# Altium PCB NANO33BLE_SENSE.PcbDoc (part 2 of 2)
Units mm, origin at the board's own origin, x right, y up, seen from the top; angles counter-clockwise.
Board outline 43.18 x 17.78 mm, 4 copper layers (TOP, GND, SIG, BOTTOM), stack 1.586 mm thick; 73 components, 66 nets, 343 pads, 193 vias.
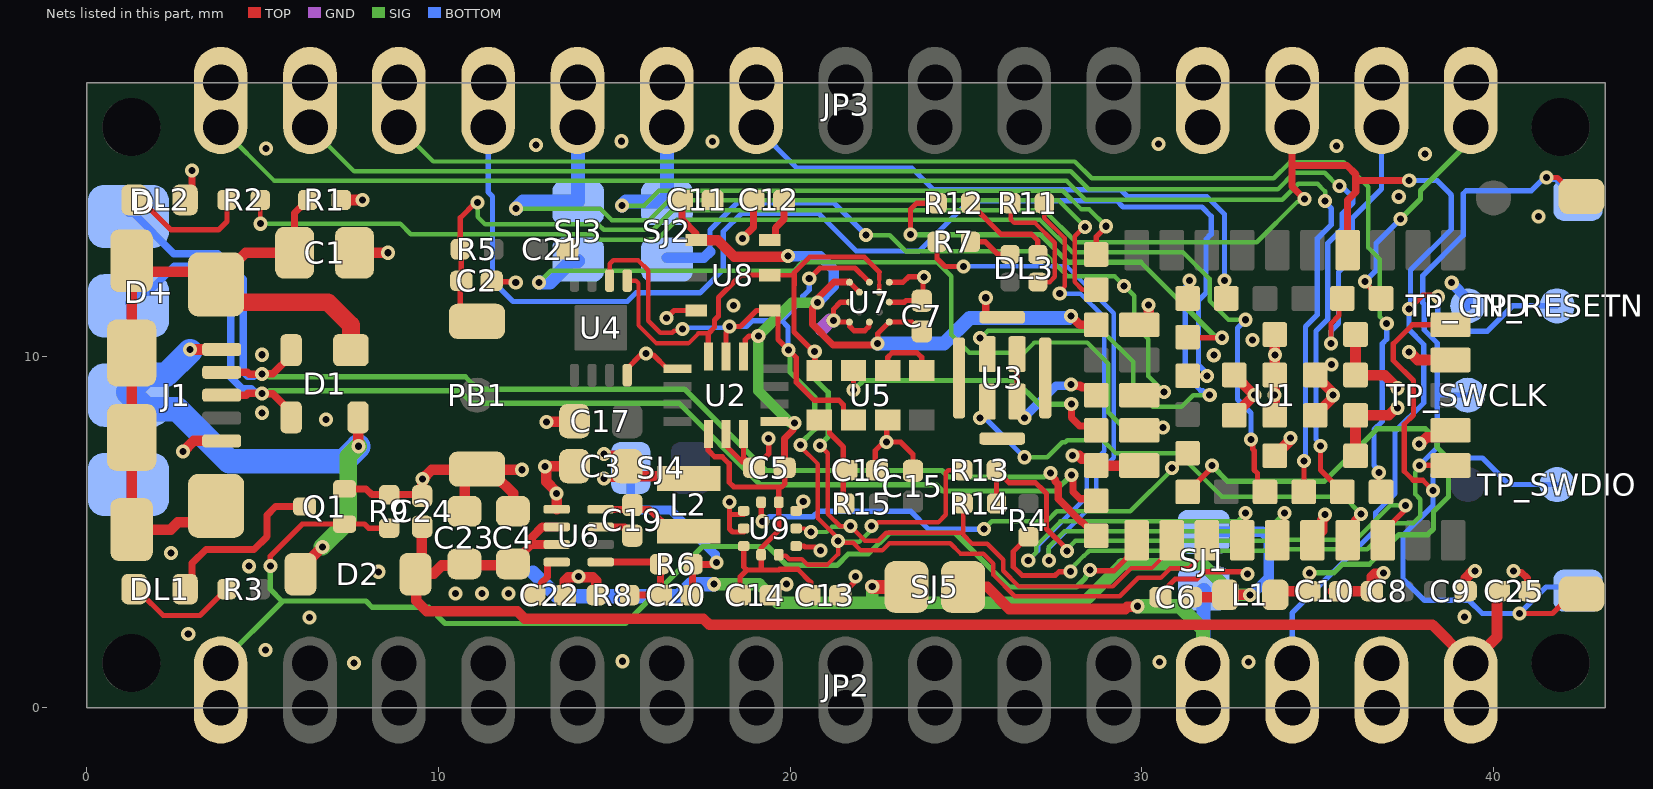
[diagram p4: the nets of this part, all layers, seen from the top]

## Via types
v1: diameter 0.4, hole 0.2, TOP to BOTTOM, tented both sides, 193 vias

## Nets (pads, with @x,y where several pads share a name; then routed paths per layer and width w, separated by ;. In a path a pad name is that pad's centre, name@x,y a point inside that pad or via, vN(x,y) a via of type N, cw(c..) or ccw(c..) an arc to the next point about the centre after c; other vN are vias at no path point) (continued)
D6~: JP3.9 U1.41 | length 16.8
  TOP w0.15: v1(32.352,12.149) 32.352,11.69 U1.41@32.402,11.64
  BOTTOM w0.15: JP3.9@19.035,16.51 20.202,15.343 23.461,15.343 24.073,14.732 29.398,14.732 29.591,14.538 31.847,14.538 32.352,14.034 v1(32.352,12.149)
D7: JP3.10 SJ2.2 U1.47 | length 18.9
  TOP w0.127: JP3.10@16.403,16.418 JP3.10@16.495,16.51
  TOP w0.15: U1.47@28.702,12.89 28.702,13.392 28.986,13.676 v1(28.986,13.694)
  SIG w0.127: v1(15.216,14.283) 15.853,14.283 16.274,14.704 27.753,14.704 28.285,14.172 28.508,14.172 v1(28.986,13.694)
  BOTTOM w0.4: v1(15.216,14.283) 15.333,14.4 SJ2.2@16.5,14.4 ; JP3.10@16.495,16.51 16.498,16.507 SJ2.2@16.498,14.402
D8: JP3.11 SJ3.2 U1.48 | length 23.2
  TOP w0.127: v1(28.387,13.678) 28.359,13.678 28.091,13.41 28.091,12.109 28.311,11.89 U1.48@28.702,11.89
  SIG w0.127: v1(12.205,14.195) 14.605,14.195 14.931,13.869 15.992,13.869 16.55,14.427 27.639,14.427 v1(28.387,13.678)
  BOTTOM w0.4: v1(12.205,14.195) 12.41,14.4 13.975,14.4 13.965,14.41 13.965,16.5 JP3.11@13.955,16.51
D9~: JP3.12 U1.44 | length 33.3
  TOP w0.15: U1.44@31.302,9.44 v1(31.852,9.44)
  BOTTOM w0.15: JP3.12@11.415,16.51 11.415,14.665 11.539,14.541 11.539,12.135 12.121,11.553 15.371,11.553 15.622,11.804 16.781,11.804 16.784,11.8 17.441,11.8 18.098,12.457 18.098,13.535 18.623,14.06 18.775,14.06 20.814,14.06 21.883,12.991 23.672,12.991 25.1,14.419 29.287,14.419 29.467,14.238 31.712,14.238 31.973,13.978 31.973,13.468 31.826,13.321 31.826,11.791 31.615,11.58 31.615,9.745 31.852,9.508 v1(31.852,9.44)
D10~: JP3.13 U1.36 | length 37.8
  TOP w0.15: v1(36.738,6.687) 36.738,6.204 U1.36@36.802,6.14
  SIG w0.127: JP3.13@8.875,16.51 9.851,15.535 14.359,15.535 16.091,15.535 28.098,15.535 28.576,15.056 33.755,15.056 34.212,15.513 35.741,15.513 36.438,14.816 36.438,13.088 36.765,12.761 36.765,11.127 v1(36.964,10.928)
  BOTTOM w0.15: v1(36.738,6.687) 36.738,6.755 36.599,6.893 36.599,7.911 36.839,8.15 36.839,10.359 36.964,10.484 v1(36.964,10.928)
GND: C1.1 C2.2 C3.1 C4.1 C5.2 C6.2 C7.1 C8.1 C9.2 C10.2 C11.2 C12.2 C13.2 C14.2 C15.1 C16.1 C17.1 C21.1 C22.1 C23.1 C24.2 C25.1 DL2.C J1.5 JP2.14 JP3.4 pad.USB_P@1.189,6.35 PB1.1 Q1.S R1.1 R8.1 R9.1 TP_GND.X U1.6 U1.12 U1.14 U1.26 U1.30 U1.53 U1.GND1 U1.GND2 U1.GND3 U1.GND4 U1.GND5 U1.GND6 U1.GND7 U1.GND8 U1.GND9 U1.GND10 U1.GND11 U1.GND12 U2.1 U2.6 U2.7 U3.5 U4.4 U5.6 U6.1 U7.A5 U7.C1 U7.C5 U7.E1 U7.E3 U8.6 U9.3 U9.5 U9.8 U9.9 | length 63.3
  TOP w0.15: C2.2@11.52,12.14 11.545,12.115 12.175,12.115 v1(12.2,12.09) ; U4.4@15.37,9.46 15.37,9.65 15.751,10.031 15.851,10.031 v1(15.899,10.079) 15.947,10.031 16.117,10.031 16.508,9.64 U2.1@17.002,9.64 ; v1(16.48,11.079) 16.702,11.3 U8.6@17.027,11.3 ; U2.6@18.177,7.79 18.227,7.74 18.227,7.405 18.639,6.993 C5.2@18.811,6.993 ; v1(18.28,5.85) 18.277,5.848 18.277,5.507 ; U2.7@18.678,7.79 18.678,7.127 C5.2@18.811,6.993 ; U9.9@18.682,5 18.365,5 18.277,5.088 18.277,5.507 ; U9.8@18.682,5.5 18.284,5.5 18.277,5.507 ; C5.2@18.878,6.993 C5.2@18.811,6.993 ; v1(19.391,7.664) 19.391,7.216 19,6.825 C5.2@18.977,6.825 18.977,6.827 C5.2@18.811,6.993 ; C14.2@19.447,3.205 19.513,3.205 19.776,3.468 19.853,3.468 v1(19.901,3.516) ; U9.3@20.172,4.6 20.396,4.6 20.421,4.575 20.702,4.575 20.801,4.476 v1(20.869,4.476) ; U9.5@20.172,5.6 20.197,5.6 20.327,5.73 20.327,5.817 v1(20.375,5.865) ; C13.2@21.426,3.205 21.451,3.205 21.812,3.566 21.812,3.684 v1(21.86,3.732) ; U7.E1@21.687,10.97 21.274,10.97 v1(21.232,11.012) 21.232,11.333 21.434,11.535 U7.C1@21.688,11.535 ; U7.E1@21.688,10.969 21.688,10.854 21.82,10.721 22.121,10.721 22.244,10.844 U7.E3@22.244,10.959 ; U7.E3@22.231,10.959 U7.E3@22.244,10.959 ; U7.E3@22.254,10.969 U7.E3@22.244,10.959 ; C16.1@22.423,6.825 22.423,7.315 22.617,7.508 22.629,7.508 22.677,7.557 23.144,7.557 23.494,7.207 C15.1@23.494,6.74 ; v1@22.75,7.557 22.75,8.167 U5.6@22.774,8.19 ; U7.C5@22.82,11.535 23.247,11.535 23.297,11.585 23.735,11.585 C7.1@23.745,11.575 23.779,11.609 23.779,12.221 v1(23.813,12.255) 23.366,12.255 23.212,12.101 U7.A5@22.82,12.101 ; U1.53@28.677,6.915 U1.53@28.702,6.89 ; C6.2@30.53,3.148 30.723,3.341 30.723,3.435 30.951,3.663 31.56,3.663 31.77,3.873 32.953,3.873 v1@33.009,3.816
  TOP w0.2: DL2.C@3,14.44 v1(3,15.275) ; Q1.S@7.335,6.225 7.944,6.225 8.109,6.06 R9.1@8.6,6.06 9.546,6.06 9.548,6.06 9.546,6.061 9.544,6.064 9.544,6.504 9.546,6.507 v1(9.548,6.508) ; v1(18.65,13.35) 18.65,13.357 18.957,13.664 C12.2@18.957,14.44 ; U3.5@25.563,11.149 v1@25.563,11.645 ; U3.5@25.755,11.106 U3.5@26.23,11.106 ; v1(40.57,3.89) 40.608,3.852 40.799,3.852 40.961,3.69 C25.1@40.961,3.309
  TOP w0.3: v1(2.74,7.287) 3.043,7.59 J1.5@3.84,7.59 ; R1.1@7.24,14.44 v1(7.84,14.44) ; C1.1@7.615,12.94 v1(8.565,12.94) ; C24.2@9.54,5.92 C24.2@9.55,5.91 ; C24.2@9.546,5.949 9.546,6.06 9.546,6.061 v1@9.546,6.507 ; v1(9.548,6.508) 9.81,6.77 11.088,6.77 10.745,6.427 10.745,5.565 10.74,5.57 C23.1@10.74,5.58 ; PB1.1@11.1,6.775 11.633,6.775 PB1.1@11.633,6.77 ; C4.1@12.12,5.57 12.13,5.56 C4.1@12.13,5.55 ; C4.1@12.125,5.57 12.125,6.097 11.633,6.589 PB1.1@11.633,6.77 ; v1(12.38,6.77) PB1.1@11.633,6.77 ; v1(13.073,8.127) 13.084,8.139 13.859,8.139 C17.1@13.87,8.15 ; U6.1@13.365,5.645 v1(13.365,6.095) 13.365,6.145 13.356,6.145 13.065,6.435 13.065,6.831 v1(13.037,6.859) 13.042,6.865 13.865,6.865 C3.1@13.87,6.87 ; C22.1@13.6,3.125 C22.1@13.6,3.205 13.6,3.618 13.697,3.715 14.392,3.715 14.49,3.617 R8.1@14.49,3.205 R8.1@14.49,3.125 ; v1(28.031,7.181) 28.051,7.162 28.224,7.162 28.295,7.09 28.502,7.09 U1.53@28.677,6.915 ; U1.53@28.702,6.89 U1.30@29.927,6.89 ; U1.26@29.927,10.89 29.997,10.89 30.197,11.09 v1(30.197,11.451) ; U1.GND12@32.622,9.465 U1.GND12@32.627,9.465 v1(33.202,8.89) U1.GND11@32.627,8.315 ; U1.GND7@33.777,7.165 34.227,7.615 v1(34.227,7.677) ; U1.GND8@33.777,8.315 v1(33.777,8.89) U1.GND9@33.777,9.465 33.783,9.471 v1(33.783,10.039) 33.783,10.609 U1.GND10@33.777,10.615 ; U1.6@34.852,4.765 35.127,5.04 35.127,5.339 35.213,5.425 v1(35.213,5.493) ; U1.GND5@34.927,8.315 35.434,8.822 v1(35.434,8.889) 35.386,8.937 35.386,9.006 U1.GND6@34.927,9.465 ; C10.2@35.435,3.312 35.439,3.316 36.536,3.316 C8.1@36.54,3.32 ; U1.GND1@36.077,7.165 U1.GND2@36.077,8.315 37.025,8.315 37.242,8.532 v1(37.269,8.532) ; U1.GND4@36.077,10.615 U1.GND3@36.077,9.465 36.087,9.455 36.903,9.455 v1(37.271,9.087) ; C8.1@36.47,3.39 C8.1@36.54,3.32 ; C8.1@36.542,3.322 C8.1@36.54,3.32 ; v1(36.87,3.84) 36.845,3.815 36.628,3.815 36.54,3.727 C8.1@36.54,3.32 ; v1(37.593,10.117) 37.62,10.117 37.847,9.89 U1.14@38.777,9.89 ; v1(37.888,7.509) 37.915,7.509 38.096,7.69 38.564,7.69 U1.12@38.77,7.897 ; C9.2@39.21,3.32 39.21,3.685 v1@39.415,3.89
  GND w0.4: 20.9,10.775 21.137,11.012 v1(21.232,11.012)
  BOTTOM w0.3: v1@38.806,12.082 39.268,11.619 TP_GND.X@39.268,11.43
  other v1: 7.6,1.275 15.23,1.325 30.498,1.309 33.038,1.309 5.088,1.647 2.889,2.102 6.342,2.564 39.17,2.59 10.49,3.249 11.24,3.249 11.99,3.249 13.99,3.733 33,3.8 8.294,3.869 39.47,3.89 4.611,4.027 2.4,4.4 22.745,7.557 6.8,8.2 4.99,8.39 35.393,9.765 4.99,10.04 32.047,10.026 33.144,10.465 18.393,11.437 25.563,11.661 38.812,12.087 41.283,13.974 37.306,14.533 38.053,15.746 5.1,15.9 35.534,15.97 12.771,16.002 30.48,16.037 15.21,16.11 17.8,16.1
INT_APDS: U1.52 U5.2 | length 8.2
  TOP w0.15: v1(21.801,9.042) U5.2@21.801,9.588 ; U5.2@22.001,9.588 U5.2@22.004,9.59
  TOP w0.2: v1(27.995,8.635) 27.995,8.252 28.227,8.02 28.572,8.02 U1.52@28.702,7.89
  SIG w0.15: v1@21.896,9.122 22.085,9.311 26.401,9.311 27.077,8.635 v1(27.995,8.635)
LB: R12.1 U1.43 | length 12.6
  TOP w0.15: v1(23.425,13.454) 23.425,14.175 23.6,14.35 R12.1@24.18,14.35 ; U1.43@31.302,10.54 31.318,10.524 v1(32.286,10.524)
  SIG w0.15: v1(23.425,13.454) 27.117,13.454 27.9,12.671 29.971,12.671 32.07,10.572 32.238,10.572 v1(32.286,10.524)
LG: R11.1 U1.4 | length 19.9
  TOP w0.127: R11.1@27.23,14.35 27.23,13.93 27.814,13.346 27.814,11.989 27.668,11.843 v1(27.668,11.778)
  TOP w0.15: U1.4@32.852,4.765 32.952,4.865 v1(32.952,5.535)
  SIG w0.127: v1(26.772,4.19) 27.004,4.422 27.004,4.615 27.688,5.299 32.717,5.299 v1(32.952,5.535)
  BOTTOM w0.127: v1(26.772,4.19) 27.054,4.472 27.054,4.622 28.431,5.999 28.431,6.797 28.93,7.296 28.93,11.104 28.255,11.778 v1(27.668,11.778)
LPS22HBTR_INT1: U1.46 U9.7 | length 13.8
  TOP w0.15: U9.7@19.177,5.745 19.177,5.343 v1(19.215,5.305) ; v1(30.861,6.82) 30.882,6.82 U1.46@31.302,7.24
  SIG w0.127: v1(25.514,5.091) 25.731,5.308 27.305,5.308 27.583,5.587 29.674,5.587 30.861,6.773 v1(30.861,6.82)
  BOTTOM w0.15: v1(19.215,5.305) 19.282,5.305 19.413,5.436 20.656,5.436 20.814,5.594 23.424,5.594 23.94,5.078 25.501,5.078 v1(25.514,5.091)
LR: R7.1 U1.5 | length 22.3
  TOP w0.15: R7.1@24.18,13.25 24.18,12.773 24.403,12.55 v1(24.93,12.55) ; U1.5@33.852,4.765 34.052,4.965 v1(34.052,5.535)
  SIG w0.127: v1(27.36,4.186) 27.36,4.58 27.802,5.022 33.54,5.022 v1(34.052,5.535)
  BOTTOM w0.127: v1(24.93,12.55) 27.876,12.55 29.207,11.219 29.207,7.115 28.708,6.616 28.708,5.884 27.36,4.536 v1(27.36,4.186)
MIC_PWR: U1.51 U3.1 U3.2 | length 4.4
  TOP w0.15: U3.1@26.455,8.706 U3.2@26.455,10.056
  TOP w0.25: U3.1@26.455,8.706 26.455,8.436 26.645,8.246 v1(26.665,8.246) ; v1(27.99,9.19) 28.019,9.161 28.248,9.161 28.294,9.115 28.477,9.115 U1.51@28.702,8.89
  BOTTOM w0.25: v1@26.672,8.272 27.561,9.161 27.961,9.161 v1(27.99,9.19)
MISO~: JP3.15 U1.34 | length 41.5
  TOP w0.15: U1.34@34.602,6.14 34.609,6.147 v1(34.609,7.016)
  SIG w0.127: JP3.15@3.81,16.51 5.339,14.981 14.589,14.981 15.861,14.981 27.868,14.981 28.4,14.449 33.996,14.449 34.445,14.898 34.996,14.898 35.211,14.683 35.211,14.411 v1(35.214,14.408)
  BOTTOM w0.15: v1(34.609,7.016) 34.652,7.058 34.652,10.84 34.991,11.179 34.991,13.34 35.39,13.739 35.39,14.196 35.214,14.372 v1(35.214,14.408)
MOSI: JP3.14 U1.35 | length 40
  TOP w0.15: v1(35.082,7.441) 35.082,6.76 U1.35@35.702,6.14
  SIG w0.127: JP3.14@6.35,16.51 7.603,15.258 14.474,15.258 15.976,15.258 27.983,15.258 28.492,14.749 33.872,14.749 34.336,15.213 35.201,15.213 35.581,14.834 v1(35.617,14.834)
  BOTTOM w0.15: v1(35.082,7.441) 35.082,7.509 34.952,7.638 34.952,10.716 35.291,11.055 35.291,13.216 35.69,13.615 35.69,14.05 36,14.36 36,14.509 35.676,14.834 v1(35.617,14.834)
NetC3_2: C3.2 C20.2 L2.2 R6.2 SJ4.1 | length 10
  TOP w0.2: v1(14.71,6.52) C3.2@15.37,6.52 ; v1(14.71,7.22) C3.2@15.37,7.22 ; C20.2@17.22,3.225 17.22,4.08 17.242,4.058 17.266,4.082 17.802,4.082 17.851,4.131 v1(17.905,4.131)
  TOP w0.25: C3.2@15.37,6.87 15.661,6.579 C3.2@15.729,6.579
  TOP w0.3: C3.2@15.729,6.579 17.111,6.579 L2.2@17.17,6.52
  BOTTOM w0.2: v1(14.71,6.52) SJ4.1@15.17,6.52 ; v1(14.71,7.22) 14.717,7.213 SJ4.1@15.077,7.213
  BOTTOM w0.25: SJ4.1@15.47,6.82 15.47,5.773 15.616,5.627 16.606,5.627 17.876,4.356 17.876,4.16 v1(17.905,4.131)
NetC10_1: C10.1 L1.2 U1.31 | length 16.8
  TOP w0.15: U1.31@31.302,6.14 31.997,6.836 v1(31.997,6.888) ; L1.2@33.798,3.213 L1.2@33.897,3.312 ; C10.1@34.765,3.312 34.767,3.315 34.767,3.837 v1(34.77,3.84)
  TOP w0.3: L1.2@33.897,3.312 C10.1@34.765,3.312
  SIG w0.15: v1(31.997,6.888) 32.441,6.444 35.195,6.444 36.684,7.934 38.064,7.934 38.4,7.598 38.4,7.401 38.717,7.084 38.717,6.002 38.291,5.576 38.291,5.089 38.127,4.925 37.313,4.925 36.809,4.42 36.806,4.42 36.468,4.083 35.709,4.083 35.466,3.84 v1(34.77,3.84)
NetC12_1: C12.1 U8.3 | length 1.4
  TOP w0.2: U8.3@19.35,13.266 19.474,13.266 19.582,13.375 19.582,13.649 19.827,13.894 C12.1@19.827,14.44
NetC16_2: C16.2 R15.1 U5.8 | length 2.4
  TOP w0.15: U5.8@21.034,8.05 21.119,7.965 21.119,7.814 21.514,7.419 R15.1@21.514,5.86
NetC19_1: C19.1 L2.1 U6.8 | length 3
  TOP w0.2: U6.8@14.615,5.645 15.345,5.645 15.515,5.815 15.695,5.635 16.005,5.635 16.62,5.02 L2.1@17.17,5.02
NetC19_2: C19.2 U6.7 | length 1
  TOP w0.2: U6.7@14.615,5.145 15.313,5.145 15.513,4.945 C19.2@15.515,4.945
NetC20_1: C20.1 R6.1 R8.2 U6.5 | length 3.4
  TOP w0.2: U6.5@14.615,4.145 R6.1@16.23,4.145 ; R8.2@15.44,3.205 C20.1@16.33,3.205 ; R6.1@16.29,4.085 16.31,4.065 C20.1@16.31,3.225
NetC22_2: C22.2 U6.4 | length 1.2
  TOP w0.2: C22.2@12.73,3.205 12.914,3.389 12.914,3.541 13.098,3.726 13.098,4.12 13.123,4.145 U6.4@13.177,4.145
NetDL1_A: DL1.A R3.1 | length 3.1
  TOP w0.15: DL1.A@1.55,3.375 1.55,3.253 2.176,2.626 3.223,2.626 3.972,3.375 R3.1@3.99,3.375
NetDL1_C: DL1.C Q1.D | length 5
  TOP w0.2: DL1.C@3,3.375 3,4.111 3.391,4.503 4.761,4.503 5.124,4.866 5.124,5.477 5.372,5.725 Q1.D@6.195,5.725
NetDL2_A: DL2.A R2.1 | length 3.5
  TOP w0.15: DL2.A@1.55,14.44 1.55,14.422 1.827,14.145 1.845,14.145 2.398,13.592 3.75,13.592 3.99,13.832 R2.1@3.99,14.44
NetDL3_2: DL3.2 R7.2 | length 1.3
  TOP w0.15: R7.2@25.13,13.25 25.555,13.25 25.91,12.895 DL3.2@26.255,12.895
NetDL3_3: DL3.3 R12.2 | length 2.8
  TOP w0.15: R12.2@25.13,14.35 25.13,14.335 26,13.465 26.861,13.465 27.045,13.282 DL3.3@27.045,12.895
NetDL3_4: DL3.4 R11.2 | length 3.5
  TOP w0.127: R11.2@26.28,14.35 26.28,13.874 26.368,13.787 26.964,13.787 27.528,13.222 27.528,12.255 27.378,12.105 DL3.4@27.045,12.105
NetJP2_12: JP2.12 SJ1.2 SJ5.2 | length 10.5
  TOP w0.3: SJ5.2@24.87,3.439 25.608,3.439 26.237,2.81 29.528,2.81 29.588,2.87 29.856,2.87 v1(29.875,2.889)
  SIG w0.4: v1(29.875,2.889) 31.072,2.889 31.735,2.227 JP2.12@31.735,1.27
  BOTTOM w0.4: JP2.12@31.75,1.27 31.756,1.276 31.756,3.344 SJ1.2@31.762,3.35
NetR2_2: R2.2 U1.33 | length 36
  TOP w0.127: v1(4.94,13.765) R2.2@4.94,14.44
  TOP w0.15: v1(33.105,7.631) 33.152,7.584 33.152,7.36 33.195,7.317 33.195,6.766 33.29,6.671 33.29,6.352 U1.33@33.502,6.14
  SIG w0.127: v1(4.94,13.765) 8.923,13.765 9.219,13.469 14.431,13.469 14.585,13.315 16.222,13.315 16.779,13.873 27.106,13.873 28.019,12.959 31.165,12.959 31.927,12.197 31.927,11.573 32.465,11.035 v1(32.952,11.035)
  BOTTOM w0.15: v1(32.952,11.035) 32.719,10.802 32.719,8.772 33.105,8.386 v1(33.105,7.631)
NetSJ2_1: SJ2.1 U1.28 | length 19.2
  TOP w0.2: U1.28@29.927,8.89 29.981,8.944 30.599,8.944 v1(30.637,8.983)
  SIG w0.127: v1(22.157,13.44) 22.835,13.44 23.292,12.983 27.179,12.983 27.888,12.275 29.225,12.275 v1(29.5,12) 29.783,11.717 29.783,10.891 30.19,10.485 30.19,9.43 v1(30.637,8.983)
  BOTTOM w0.15: 17.723,12.971 17.723,13.585 18.504,14.365 21.232,14.365 v1(22.157,13.44)
  BOTTOM w0.3: SJ2.1@16.5,12.795 17.547,12.795 17.723,12.971
NetSJ3_1: SJ3.1 U1.29 | length 24.1
  TOP w0.15: U1.29@29.927,7.89 30.007,7.97 v1(30.599,7.97)
  SIG w0.127: v1(12.856,12.089) 13.198,12.431 20.113,12.431 20.35,12.669 24.184,12.669 24.58,12.273 24.58,10.613 25.091,10.102 26.663,10.102 26.948,10.388 28.447,10.388 29.045,9.79 29.045,8.405 29.119,8.331 29.596,7.854 30.024,7.854 30.141,7.97 v1(30.599,7.97)
  BOTTOM w0.4: v1(12.856,12.089) 13.167,12.089 13.778,12.7 SJ3.1@13.975,12.7
NetU5_3: U5.3 U5.4 | length 1.8
  TOP w0.15: U5.3@22.774,9.59 22.774,9.965 22.905,10.097 23.612,10.097 23.744,9.965 U5.4@23.744,9.59
PDMCLK: U1.42 U3.3 | length 12.6
  TOP w0.15: v1(25.395,10.516) 25.605,10.306 U3.3@25.605,10.056 ; U1.42@31.302,11.64 31.352,11.69 v1(31.352,12.149)
  SIG w0.127: v1@25.532,10.632 25.626,10.726 28.868,10.726 29.753,9.842 29.753,9.118 30.314,8.558 31.129,8.558 31.462,8.891 v1(31.931,8.891)
  BOTTOM w0.15: v1(31.352,12.149) 31.352,12.081 31.236,11.965 31.236,9.455 31.676,9.015 31.74,9.015 31.864,8.891 v1(31.931,8.891)
PDMDIN: U1.7 U3.4 | length 13.7
  TOP w0.15: v1(25.395,8.246) 25.605,8.456 U3.4@25.605,8.706
  TOP w0.2: U1.7@35.852,4.765 36.046,4.959 36.046,5.334 v1(36.228,5.516)
  SIG w0.127: v1(26.659,7.125) 27.31,7.125 27.74,7.555 27.821,7.555 27.879,7.613 28.888,7.613 29.268,7.233 31.049,7.233 32.275,6.007 35.737,6.007 v1(36.228,5.516)
  BOTTOM w0.15: v1@25.555,8.23 v1(26.659,7.125)
R_PULLUP: R13.2 R14.2 U1.8 | length 15.9
  TOP w0.15: R13.2@25.863,6.76 R13.2@25.867,6.757 ; R14.2@25.87,5.81 25.867,5.813 R13.2@25.867,6.757 ; v1@27.875,4.51 27.87,4.51 27.294,5.086 27.294,6.096 27.125,6.265 27.114,6.265 26.978,6.401 26.222,6.401 R13.2@25.867,6.757 ; U1.8@36.852,4.765 36.852,4.99 37.446,5.584 37.446,5.709 v1(37.494,5.757)
  SIG w0.127: v1@27.875,4.51 28.11,4.745 33.864,4.745 33.903,4.784 36.097,4.784 37.07,5.757 v1(37.494,5.757)
  other v1: 27.875,4.46
RESETN: C2.1 JP2.13 JP3.3 PB1.2 R5.1 TP_RESETN.X U1.19 | length 59.4
  TOP w0.15: C2.1@10.625,12.14 10.625,11.402 PB1.2@11.037,10.99 ; R5.1@10.625,13.04 10.625,13.935 11.055,14.365 v1(11.114,14.365) ; C2.1@10.65,12.14 R5.1@10.65,13.04 ; v1(37.594,11.341) 37.991,11.738 38.369,11.738 v1(38.417,11.69)
  TOP w0.2: JP3.3@34.275,16.51 34.521,16.264 34.275,16.017 34.275,15.418 ; v1(34.621,14.473) 34.275,14.819 34.275,15.418 ; U1.19@35.852,13.015 35.852,14.432 36.083,14.663 36.083,14.917 ; v1(37.604,14.995) 36.161,14.995 36.083,14.917 ; 34.275,15.418 35.836,15.418 36.083,15.171 36.083,14.917
  SIG w0.127: v1(11.114,14.365) 11.114,13.967 11.336,13.746 14.546,13.746 14.7,13.592 16.107,13.592 16.665,14.15 27.221,14.15 28.134,13.236 33.266,13.236 34.413,14.383 34.458,14.383 34.547,14.473 v1(34.621,14.473)
  BOTTOM w0.15: JP2.13@34.275,1.27 34.275,2.695 36.653,5.073 36.653,5.547 37.2,6.094 37.2,7.855 38.018,8.673 38.018,10.33 37.594,10.754 v1(37.594,11.341) 37.642,11.389 37.642,12.447 38.798,13.602 38.798,14.566 38.78,14.584 38.78,14.612 38.397,14.995 v1(37.604,14.995) ; v1(38.417,11.69) 38.417,11.066 38.778,10.705 39.82,10.705 40.545,11.43 TP_RESETN.X@41.808,11.43
RX: JP3.2 U1.38 | length 8.2
  TOP w0.15: v1(35.377,10.36) 35.377,10.922 35.607,11.153 35.607,11.546 U1.38@35.702,11.64
  BOTTOM w0.15: v1(35.377,10.36) 35.377,10.716 35.591,10.93 35.591,12.392 35.99,12.792 35.99,13.926 36.815,14.75 JP3.2@36.815,16.51
SCK: JP2.1 Q1.G R9.2 U1.1 | length 35.2
  TOP w0.15: v1(5.223,4.034) 5.223,4.315 6.133,5.225 Q1.G@7.335,5.225 7.899,5.225 8.014,5.11 R9.2@8.6,5.11 ; v1(28.526,3.916) 28.544,3.899 29.211,3.899 29.852,4.54 U1.1@29.852,4.765
  SIG w0.15: JP2.1@3.81,1.27 5.578,3.038 7.941,3.038 8.117,2.862 9.727,2.862 10.192,2.397 15.322,2.397 17.512,4.586 19.376,4.586 19.911,4.051 21.33,4.051 21.654,4.375 22.224,4.375 22.822,4.973 24.691,4.973 26.225,3.439 28.141,3.439 28.397,3.695 28.397,3.719 28.526,3.849 v1(28.526,3.916) ; v1(5.223,4.034) 5.223,3.363 5.563,3.023
SCL1: R13.1 U1.3 U2.13 U4.6 U5.7 U7.A3 U8.1 U9.2 | length 44.7
  TOP w0.127: U4.6@14.87,12.15 14.87,12.63 14.97,12.73 15.678,12.73 15.967,12.441 15.967,11.007 16.309,10.665 16.652,10.665 16.709,10.722 16.886,10.722 v1(16.939,10.774) ; U9.2@19.677,4.355 19.706,4.326 19.88,4.326 19.977,4.229 20.338,4.229 20.504,4.062 21.052,4.062 21.363,4.374 v1@21.363,4.691 ; v1(20.293,7.47) 20.293,7.433 20.793,6.933 20.793,5.389 21.254,4.929 21.254,4.924 21.363,4.814 v1(21.363,4.74) 21.412,4.691 21.798,4.691 22.013,4.475 22.618,4.475 22.825,4.682 24.551,4.682 24.846,4.388 25.49,4.388 25.781,4.096 25.781,3.78 26.387,3.174 29.377,3.174 29.903,3.699 30.545,3.699 30.809,3.963 31.327,3.963 31.577,4.213 31.577,4.49 U1.3@31.852,4.765 ; v1(22.315,5.169) 22.389,5.169 22.501,5.281 24.218,5.281 24.425,5.488 24.425,6.686 24.499,6.76 R13.1@25.013,6.76
  TOP w0.15: U2.13@18.177,9.99 18.177,10.672 18.279,10.774 v1(18.279,10.841) 18.588,10.841 19.047,11.3 19.557,11.3 19.657,11.2 19.657,10.475 20.177,9.955 20.177,9.255 20.685,8.747 21.387,8.747 21.519,8.616 21.519,8.415 21.744,8.19 U5.7@21.775,8.19 ; v1(20.545,12.205) 20.847,12.507 21.848,12.507 U7.A3@22.254,12.101 ; U5.7@21.975,8.19 U5.7@22.004,8.19
  SIG w0.127: v1(21.363,4.74) 21.387,4.717 21.965,4.717 22.263,5.014 22.263,5.117 v1(22.315,5.169)
  SIG w0.15: v1(19.953,10.179) 19.999,10.133 19.999,9.541 20.698,8.841 20.698,8.602 20.7,8.6 20.7,7.921 20.293,7.513 v1(20.293,7.47)
  BOTTOM w0.127: v1(16.939,10.774) 16.972,10.808 18.245,10.808 v1(18.279,10.841)
  BOTTOM w0.15: v1(18.279,10.841) 18.762,10.841 18.931,11.01 19.705,11.01 19.763,11.01 ; v1(19.953,10.179) 19.943,10.189 19.943,10.829 19.763,11.01 ; v1(20.545,12.205) 20.545,11.884 20.361,11.7 20.361,11.608 19.763,11.01
SDA1: R14.1 U1.2 U2.14 U4.5 U5.1 U7.B4 U8.2 U9.4 | length 33.9
  TOP w0.108: 22.537,12.028 22.537,12.168
  TOP w0.127: U4.5@15.37,12.15 15.615,12.15 15.69,12.075 15.69,10.873 16.202,10.361 17.11,10.361 17.394,10.645 17.677,10.645 ; U8.2@19.427,12.3 20.12,12.3 ; U9.4@20.172,5.1 20.424,5.1 20.524,5 v1(20.597,5) ; v1(20.846,7.465) 21.075,7.236 21.075,5.514 21.423,5.166 v1(21.719,5.166) 22.129,4.755 22.507,4.755 22.733,4.981 24.92,4.981 ; U7.B4@22.537,11.818 22.537,12.028 ; 22.537,12.168 22.537,12.393 ; R14.1@24.92,5.81 24.92,4.919 25.174,4.665 25.604,4.665 26.058,4.211 26.058,3.894 26.502,3.451 29.171,3.451 29.696,3.976 30.288,3.976 30.852,4.54 U1.2@30.852,4.765
  TOP w0.15: U2.14@17.677,9.99 17.677,10.645 17.854,10.822 17.854,11.029 17.963,11.137 17.963,11.663 18.608,12.308 19.419,12.308 U8.2@19.427,12.3 ; U5.1@20.926,9.59 20.701,9.815 v1(20.701,10.136) 20.665,10.136 20.113,10.689 20.113,12.022 20.12,12.029 20.12,12.3 20.12,12.381 20.56,12.821 22.109,12.821 22.537,12.393
  SIG w0.127: v1(20.597,5) 21.038,5 21.192,5.154 21.706,5.154 v1(21.719,5.166)
  SIG w0.15: v1(20.701,10.136) 20.701,9.803 20.57,9.673 20.57,9.486 21.082,8.974 21.082,7.702 v1(20.846,7.465)
SHIELD: C1.2 D1.1 J1.M1 J1.M2 J1.M3 J1.M4 J1.M5 J1.M6 R1.2 | length 21.2
  TOP w0.2: C1.2@5.915,12.94 5.915,14.072 6.175,14.332 R1.2@6.175,14.44
  TOP w0.3: J1.M2@1.28,12.71 J1.M5@1.28,10.09 J1.M6@1.28,7.69 J1.M3@1.28,5.07 2.39,5.07 2.596,5.276 J1.M4@3.213,5.276 ; J1.M2@1.588,12.402 3.316,12.402 J1.M1@3.68,12.037 3.68,12.091 4.529,12.94 C1.2@5.915,12.94
  TOP w0.5: J1.M1@3.68,12.037 4.181,11.537 6.863,11.537 7.515,10.885 D1.1@7.515,10.17
SWCLK: pad.JTAG_PAD@42.403,14.444 pad.JTAG_PAD@42.503,14.544 R4.1 TP_SWCLK.X U1.11 | length 29.6
  TOP w0.15: R4.1@26.779,4.86 26.764,4.86 26.347,4.443 26.347,4.014 26.6,3.761 27.536,3.761 27.647,3.871 v1(27.972,3.871) ; v1(37.895,6.897) 38.77,6.897 U1.11@38.777,6.89 ; v1(41.511,15.079) 41.818,15.079 42.253,14.644 pad.JTAG_PAD@42.303,14.644
  SIG w0.127: v1(27.972,3.871) 27.972,3.941 28.113,4.082 28.113,4.087 28.355,4.33 28.368,4.33 28.507,4.468 34.011,4.468 34.05,4.507 36.41,4.507 37.158,5.255 37.72,5.255 37.919,5.454 37.919,5.933 37.772,6.08 37.772,6.705 37.895,6.829 v1(37.895,6.897)
  BOTTOM w0.15: v1(37.895,6.897) 38.4,7.401 38.4,8.892 ; TP_SWCLK.X@39.266,8.892 38.4,8.892 ; pad.JTAG_PAD@42.003,14.644 42.003,14.793 41.795,15.001 41.795,15.03 41.628,15.03 41.579,15.079 41.453,15.079 41.08,14.707 39.228,14.707 39.14,14.619 39.14,13.44 37.992,12.292 37.992,11.514 38.032,11.474 38.032,10.741 38.4,10.372 38.4,8.892
SWDIO: pad.JTAG_PAD@42.403,3.336 pad.JTAG_PAD@42.503,3.236 TP_SWDIO.X U1.15 | length 21.7
  TOP w0.15: v1(38.277,6.183) 37.988,6.472 37.719,6.472 37.463,6.728 37.463,8.065 37.723,8.325 37.723,9.307 37.149,9.881 37.149,10.349 37.69,10.89 U1.15@38.777,10.89 ; v1(40.743,2.681) 41.676,2.681 42.131,3.136 pad.JTAG_PAD@42.303,3.136
  BOTTOM w0.15: TP_SWDIO.X@41.808,6.35 40.441,6.35 39.686,7.105 38.745,7.105 38.277,6.637 v1(38.277,6.183) 38.277,5.758 37.427,4.908 37.427,3.665 38.035,3.056 39.305,3.056 39.68,2.681 v1(40.743,2.681) 41.498,3.436 pad.JTAG_PAD@42.403,3.436
TX: JP3.1 U1.37 | length 6.3
  TOP w0.15: v1(36.351,12.127) 36.351,12.091 U1.37@36.802,11.64
  SIG w0.15: v1(37.352,13.899) 37.922,14.469 37.922,14.712 39.355,16.146 JP3.1@39.355,16.51
  BOTTOM w0.15: v1(36.351,12.127) 36.657,12.433 36.657,13.204 v1(37.352,13.899)
USB_N: D1.2 D-.X J1.2 pad.USB_N U1.55 | length 35.4
  TOP w0.21: J1.2@3.84,9.54 4.574,9.54 4.624,9.49 v1(4.99,9.49) 5,9.5 5.295,9.5 D1.2@5.815,10.02 ; v1(27.399,6.681) 27.399,6.629 27.544,6.485 27.544,6.435 27.624,6.355 27.624,5.944 28.283,5.285 28.307,5.285 U1.55@28.702,4.89
  SIG w0.15: v1@5.038,9.442 5.176,9.442 5.203,9.415 10.765,9.415 11.117,9.063 17,9.063 19.315,6.747 24.315,6.747 24.499,6.563 27.214,6.563 27.332,6.681 v1(27.399,6.681)
  BOTTOM w0.21: pad.USB_N@1.189,14.058 1.335,14.058 2.476,12.916 3.722,12.916 4.455,12.184 4.455,9.553 4.578,9.43 4.752,9.43 4.775,9.454 4.954,9.454 v1(4.99,9.49)
USB_P: D1.3 D+.X J1.3 pad.USB_P@1.189,11.43 U1.54 | length 35.1
  TOP w0.21: J1.3@3.84,8.89 4.534,8.89 4.584,8.94 v1(4.99,8.94) 5,8.93 5.295,8.93 D1.3@5.815,8.41 ; v1(27.999,6.623) 28.044,6.578 28.044,6.143 28.247,5.94 28.651,5.94 U1.54@28.702,5.89
  SIG w0.15: v1@5.038,8.988 5.176,8.988 5.203,9.015 10.599,9.015 10.951,8.663 16.834,8.663 19.149,6.347 24.15,6.347 24.334,6.163 27.539,6.163 v1(27.999,6.623)
  BOTTOM w0.21: pad.USB_P@1.189,11.518 1.487,11.816 pad.USB_P@1.783,11.816 ; pad.USB_P@1.783,11.849 2.49,12.556 3.573,12.556 4.095,12.035 4.095,9.404 4.428,9.07 4.682,9.07 4.775,8.976 4.954,8.976 v1(4.99,8.94)
VDD_ENV: C5.1 C7.2 C11.1 C13.1 C14.1 U1.49 U2.5 U2.8 U2.12 U7.A1 U7.B2 U7.E5 U8.4 U9.1 U9.6 U9.10 | length 37.6
  TOP w0.15: U2.5@17.677,7.79 17.677,7.315 17.853,7.139 18.069,7.139 18.27,6.938 18.27,6.412 18.402,6.28 19.669,6.28 ; C14.1@18.577,3.205 18.577,3.726 18.77,3.918 ; U2.12@18.678,9.99 18.723,10.035 18.723,10.465 18.832,10.574 v1(19.096,10.574) ; U9.10@18.682,4.5 18.682,4.006 18.77,3.918 ; U2.8@19.752,8.14 19.773,8.12 20.007,8.12 20.028,8.099 v1(20.123,8.099) ; C5.1@19.847,6.825 19.847,6.368 19.759,6.28 19.669,6.28 ; C13.1@20.589,3.322 20.589,3.57 20.218,3.941 19.709,3.941 19.687,3.918 19.177,3.918 ; U7.A1@21.684,12.105 U7.A1@21.688,12.101 U7.B2@21.971,11.818 ; v1@22.451,10.318 v1(22.489,10.356) 22.489,10.638 U7.E5@22.82,10.969 23.456,10.969 23.505,10.92 23.745,10.92 C7.2@23.745,10.705 ; 18.77,3.918 19.177,3.918 ; 19.177,3.918 U9.1@19.177,4.355 19.177,4.54 19.677,5.04 U9.6@19.677,5.845 19.677,6.273 19.669,6.28
  TOP w0.2: C11.1@16.927,14.44 16.927,13.891 17.327,13.491 U8.4@17.327,13.3 ; C5.1@19.847,6.825 19.843,6.829 19.843,7.656 20.085,7.898 20.085,8.061 v1(20.123,8.099) ; U7.A1@21.684,12.105 21.246,12.105 20.725,11.584 v1(20.786,11.524) 20.635,11.373 20.635,10.907 21.224,10.318 v1@22.451,10.318
  TOP w0.25: v1(27.99,11.14) 28.24,10.89 U1.49@28.702,10.89
  TOP w0.3: U8.4@17.327,13.3 17.939,13.3 18.416,12.823 19.854,12.823 19.857,12.825 19.922,12.825 v1(19.941,12.845)
  SIG w0.3: v1(20.123,8.099) 20.104,8.118 19.988,8.118 19.096,9.011 v1(19.096,10.574) 20.046,11.524 v1(20.786,11.524)
  BOTTOM w0.3: v1(19.941,12.845) 20.855,12.845 21.245,12.455 21.245,11.983 v1(20.786,11.524)
  BOTTOM w0.4: v1(22.489,10.356) 24.379,10.356 25.109,11.086 27.936,11.086 v1(27.99,11.14)
VIN: C4.2 C23.2 C24.1 C25.2 D2.C JP2.15 U6.2 U6.3 | length 40.3
  TOP w0.2: JP2.15@39.355,1.27 JP2.15@39.443,1.358
  TOP w0.25: C4.2@12.12,4.22 12.222,4.22 12.647,4.645 ; U6.3@13.365,4.645 12.647,4.645 ; U6.2@13.365,5.145 12.955,5.145 12.647,4.838 12.647,4.645
  TOP w0.3: D2.C@9.375,3.82 9.524,3.969 9.524,5.034 C24.1@9.54,5.05 ; C4.2@12.12,4.07 12.104,4.054 10.756,4.054 10.74,4.07 10.718,4.048 10.092,4.048 9.865,3.82 9.524,3.82 9.375,3.671 9.375,3.04 9.666,2.749 12.245,2.749 12.461,2.533 17.535,2.533 17.708,2.36 38.265,2.36 39.195,1.43 JP2.15@39.37,1.43 ; JP2.15@39.443,1.358 40.1,2.015 C25.2@40.1,3.3
VUSB: C6.1 D1.4 D2.A J1.1 L1.1 pad.USB_P@1.189,8.89 SJ1.1 SJ5.1 | length 44.7
  TOP w0.3: v1(2.938,10.187) v1(2.938,10.187) 3.838,10.189 J1.1@3.84,10.19 ; D2.A@6.08,3.8 6.08,3.955 v1(6.7,4.575) ; D1.4@7.715,8.26 7.721,8.254 7.721,7.444 v1(7.726,7.438) ; C6.1@31.4,3.148 32.313,3.148 L1.1@32.378,3.213 v1(33.073,3.213)
  TOP w0.4: v1(22.337,3.448) 22.345,3.439 SJ5.1@23.36,3.439
  SIG w0.35: v1(17.836,3.515) 19.124,3.515 19.649,2.99 22.251,2.99 ; v1@22.355,3.429 v1(22.337,3.448) 22.334,3.444 22.334,3.073 22.251,2.99 ; v1(33.073,3.213) 32.606,3.213 31.739,4.08 29.432,4.08 28.342,2.99 22.251,2.99
  SIG w0.5: v1(6.7,4.575) 7.438,5.313 7.438,7.149 v1(7.726,7.438)
  BOTTOM w0.3: SJ1.1@31.762,5.05 31.805,5.007 33.433,5.007 33.608,4.831 33.608,3.701 33.207,3.3 33.187,3.3 33.1,3.213 v1(33.073,3.213)
  BOTTOM w0.4: 12.691,3.851 13.37,3.173 16.836,3.173 17.179,3.515 v1(17.836,3.515)
  BOTTOM w0.7: v1@2.938,10.143 2.262,9.466 1.677,9.466 1.189,8.978 1.675,8.492 2.574,8.492 4.053,7.013 7.316,7.013 7.726,7.423 v1(7.726,7.438)
pads on no net: Fiducial_1.1 Fiducial_2.1 J1.4 U1.13 U1.45 U2.2 U2.3 U2.10 U2.11 U4.1 U4.2 U4.3 U4.7 U4.9 U6.6 U7.D2 U7.D4 U8.5

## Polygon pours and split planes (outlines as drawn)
GND on BOTTOM "GND_BOT" (solid, remove dead copper, pour order 19): 0,0 0,17.78 43.18,17.78 43.18,0
VUSB on BOTTOM "VUSB_POL" (solid, remove dead copper, pour order 17): 6.434,4.731 7.143,5.44 16.569,5.44 17.919,4.09 18.87,4.09 19.27,3.89 19.27,3.29 18.995,3.015 6.434,3.015
GND on GND "GND_2" (solid, remove dead copper, pour order 15): 0,17.78 0,0 43.18,0 43.18,17.78
GND on TOP "GND_TOP" (solid, remove dead copper, pour order 16): 0.091,0.425 0.091,18.205 43.271,18.205 43.271,0.425
GND on SIG "GND_3" (solid, remove dead copper, pour order 18): 0,0 0,17.78 43.18,17.78 43.18,0

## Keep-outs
TOP:
  rectangle: 21.4,10.396 23.6,12.596
GND:
  rectangle: 21.4,10.396 23.6,12.596
SIG:
  rectangle: 21.4,10.396 23.6,12.596
BOTTOM:
  rectangle: 21.4,10.396 23.6,12.596

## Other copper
TOP:
  pour cut-out: 43.162,4.137 39.352,4.137 39.352,13.633 43.162,13.633
GND:
  pour cut-out: 43.162,4.137 39.352,4.137 39.352,13.633 43.162,13.633
SIG:
  pour cut-out: 43.162,4.137 39.352,4.137 39.352,13.633 43.162,13.633
BOTTOM:
  region: 336 vertices and 0 holes, not listed, extent 0.795,2.687 1.791,3.586
  region: 243 vertices and 1 holes, not listed, extent 0.773,3.776 1.811,4.486
  pour cut-out: 15.597,14.407 17.437,14.407 17.437,12.599 15.597,12.599
  pour cut-out: 13.075,14.404 14.915,14.404 14.915,12.596 13.075,12.596
  pour cut-out: 43.162,4.137 39.352,4.137 39.352,13.633 43.162,13.633

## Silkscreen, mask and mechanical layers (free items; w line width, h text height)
Top Overlay:
  drawing of 44 lines, arcs and shapes, not listed
Bottom Overlay:
  drawing of 267 lines, arcs and shapes, not listed
Bottom Solder:
  rectangle: 15.394,6.085 17.341,7.555
Top 3D Body:
  the board outline again, w0.01
Route Tool Path:
  lines w2: -1,1 -1,0 ccw(c0,0) 0,-1 43.18,-1 ccw(c43.18,0) 44.18,0 44.18,6.5 ; -1,5 -1,13 ; -1,17 -1,17.78 cw(c0,17.78) 0,18.78 43.18,18.78 cw(c43.18,17.78) 44.18,17.78 44.18,10.5
Board:
  the board outline again, w0.1
Mechanical 5:
  lines w0.1: 0,1.27 1.27,1.27 ; 0,16.51 1.27,16.51 ; 1.27,0 1.27,1.27 ; 1.27,2.54 1.27,1.27 ; 1.27,15.24 1.27,16.51 ; 1.27,17.78 1.27,16.51 ; 2.54,1.27 1.27,1.27 ; 2.54,16.51 1.27,16.51 ; 40.64,1.27 41.91,1.27 ; 40.64,16.51 41.91,16.51 ; 41.91,0 41.91,1.27 ; 41.91,2.54 41.91,1.27 ; 41.91,15.24 41.91,16.51 ; 41.91,17.78 41.91,16.51 ; 43.18,1.27 41.91,1.27 ; 43.18,16.51 41.91,16.51 ; 0,0 43.18,0 43.18,17.78 0,17.78 0,0
SiliconCaseHole:
  lines w0.05: 19.7,6.89 19.7,10.89 25.2,10.89 25.2,13.89 28.7,13.89 28.7,6.89 19.7,6.89
Pin1added (Mech41):
  circle w0.15: c5.216,8.197 r0.05
  circle w0.15: c25.663,12.081 r0.05
  circle w0.15: c19.744,10.888 r0.05
  circle w0.15: c27.719,7.374 r0.05
  circle w0.15: c20.608,10.198 r0.05
  circle w0.15: c18.35,4 r0.05
  circle w0.15: c13.464,9.106 r0.05
  circle w0.15: c12.886,6.117 r0.05
  circle w0.15: c21.449,12.086 r0.05
  lines w0.2: 7.85,3.425 7.85,4.075 ; 1.948,3.121 2.202,3.375 1.948,3.629 1.948,3.121 ; 1.948,14.186 2.202,14.44 1.948,14.694 1.948,14.186 ; 7.15,3.4 7.15,4.05 7.85,3.75 7.15,3.4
